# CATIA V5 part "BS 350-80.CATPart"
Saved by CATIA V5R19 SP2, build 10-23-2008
Part number: BS 300-80
Bounding box of the stored display mesh (mm): x -15.868 to 15.868, y -15.868 to 15.868, z 0 to 190
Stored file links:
  C:\Users\Bora\Desktop\3D Katı model\BS serisi\BS 300\BS 300-80.CATPart
  C:\Program Files\Dassault Systemes\B19\intel_a\reffiles\standard\MetricThickPitch.txt
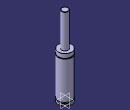
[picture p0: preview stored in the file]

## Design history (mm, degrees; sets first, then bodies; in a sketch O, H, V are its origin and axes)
Body1 (main body)
  Sketch1 on yz-plane, origin (0, 0, 0), H (0, 1, 0), V (0, 0, 1)
    point P1 (8, 189)
    point P3 (8, 189)
    point P5 (16, 99.5)
    point P6 (16, 97.5)
    point P9 (16, 99.5)
    point P14 (16, 97.5)
    line L1 (8, 189) -> (8, 109)
    arc A1 centre (7, 189) radius 1 from (8, 189) to (7, 190) ccw
    arc A2 centre (16, 98.5) radius 1 from (16, 99.5) to (16, 97.5) ccw
    line L2 (16, 0) -> (16, 4)
    line L3 (16, 99.5) -> (16, 109)
    line L4 (14.5, 7.5) -> (14.5, 4)
    line L5 (16, 7.5) -> (16, 97.5)
    line L6 (7, 190) -> (0, 190)
    point P15 (0, 190)
    line L7 (8, 109) -> (16, 109)
    line L8 (0, 0) -> (16, 0)
    line L9 (14.5, 7.5) -> (16, 7.5)
    line L10 (14.5, 4) -> (16, 4)
    coincidence: P15 V, P1 P3, P5 P9, P6 P14
    tangency: L6 A1
    horizontal: L7 H, L8 H, L9 H, L10 H
  Shaft1: profile Sketch1, axis Sketch1.V, angle 360
  Sketch2 on face of Shaft1 from Sketch1.L8, origin (0, 0, 0), H (1, 0, 0), V (0, -1, 0)
    point P1 (0, 0)
  Hole1: placed by Sketch2, at (0, 0, 0) direction (0, 0, 1), diameter 6.647, depth 4, threaded "M8", thread diameter 8, thread depth 4, pitch 1.25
